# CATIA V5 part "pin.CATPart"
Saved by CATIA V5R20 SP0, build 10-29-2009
Part number: pin
Bounding box of the stored display mesh (mm): x -25 to 184.334, y -300 to -20, z 335 to 528.094
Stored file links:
  C:\Users\Orange\Desktop\Assembly Design-8\pin.CATPart
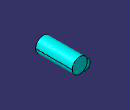
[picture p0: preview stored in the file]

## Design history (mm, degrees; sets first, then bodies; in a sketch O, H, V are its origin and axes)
Body1 (main body)
  Plane1: stored without definition
  DatumSurface1
  DatumCurve1
  DatumCurve2
  DatumSurface2
  Sketch1 on Plane1, origin (0, -50, 0), H (-1, 0, 0), V (0, 0, 1)
    circle A1 centre (-147.3338, 491.0935) radius 37
    reference projected arc E1 centre (-424.937, 360) radius 270 from (-220.4005, 183.7478) to (-220.4005, 536.2522) ccw from edge of DatumCurve1
    reference projected arc E2 centre (-424.937, 360) radius 344 from (-167.9615, 131.3089) to (-167.9615, 588.6911) ccw from edge of DatumCurve2
    tangency: A1 E1, A1 E2
  Pad1: profile Sketch1, direction (0, 1, 0), length 30, opposite side length 150
  DatumSurface3
  Plane2: stored without definition
  DatumCurve3
  Sketch2 on face of DatumSurface3, origin (0, -300, 0), H (-1, 0, 0), V (0, 0, 1)
    circle A1 centre (0, 360) radius 25
    point P2 (0, 385)
    reference projected circle E1 centre (0, 360) radius 25 from edge of DatumCurve3
    coincidence: A1 P2, P2 V, A1 E1
  Pad2: profile Sketch2, direction (0, 1, 0), length 160
  DatumCurve4
  Sketch3 on start face of Pad1, origin (0, -200, 0), H (1, 0, 0), V (0, 0, 1)
    line L1 (136.0971, 499.8349) -> (154.7096, 478.9166)
    line L2 (154.7096, 478.9166) -> (20.753, 359.7259)
    line L3 (20.753, 359.7259) -> (2.1405, 380.6441)
    line L4 (2.1405, 380.6441) -> (136.0971, 499.8349)
    construction line L5 (147.3338, 491.0935) -> (0, 360)
    point P5 (0, 360)
    point P6 (147.3338, 491.0935)
    reference projected circle E1 centre (0, 360) radius 25 from edge of DatumCurve4
    reference projected circle E2 centre (147.3338, 491.0935) radius 37 from edge [start face of Pad1 | face of Pad1 from Sketch1.A1]
    distance L4 L2 = 28
    parallelism: L1 L3
    perpendicularity: L1 L2
    coincidence: P5 V
    concentricity: P5 E1, P6 E2
    symmetry: L2 L4 L5
  Pad3: profile Sketch3, direction (0, 1, 0), length 56, opposite side length -7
